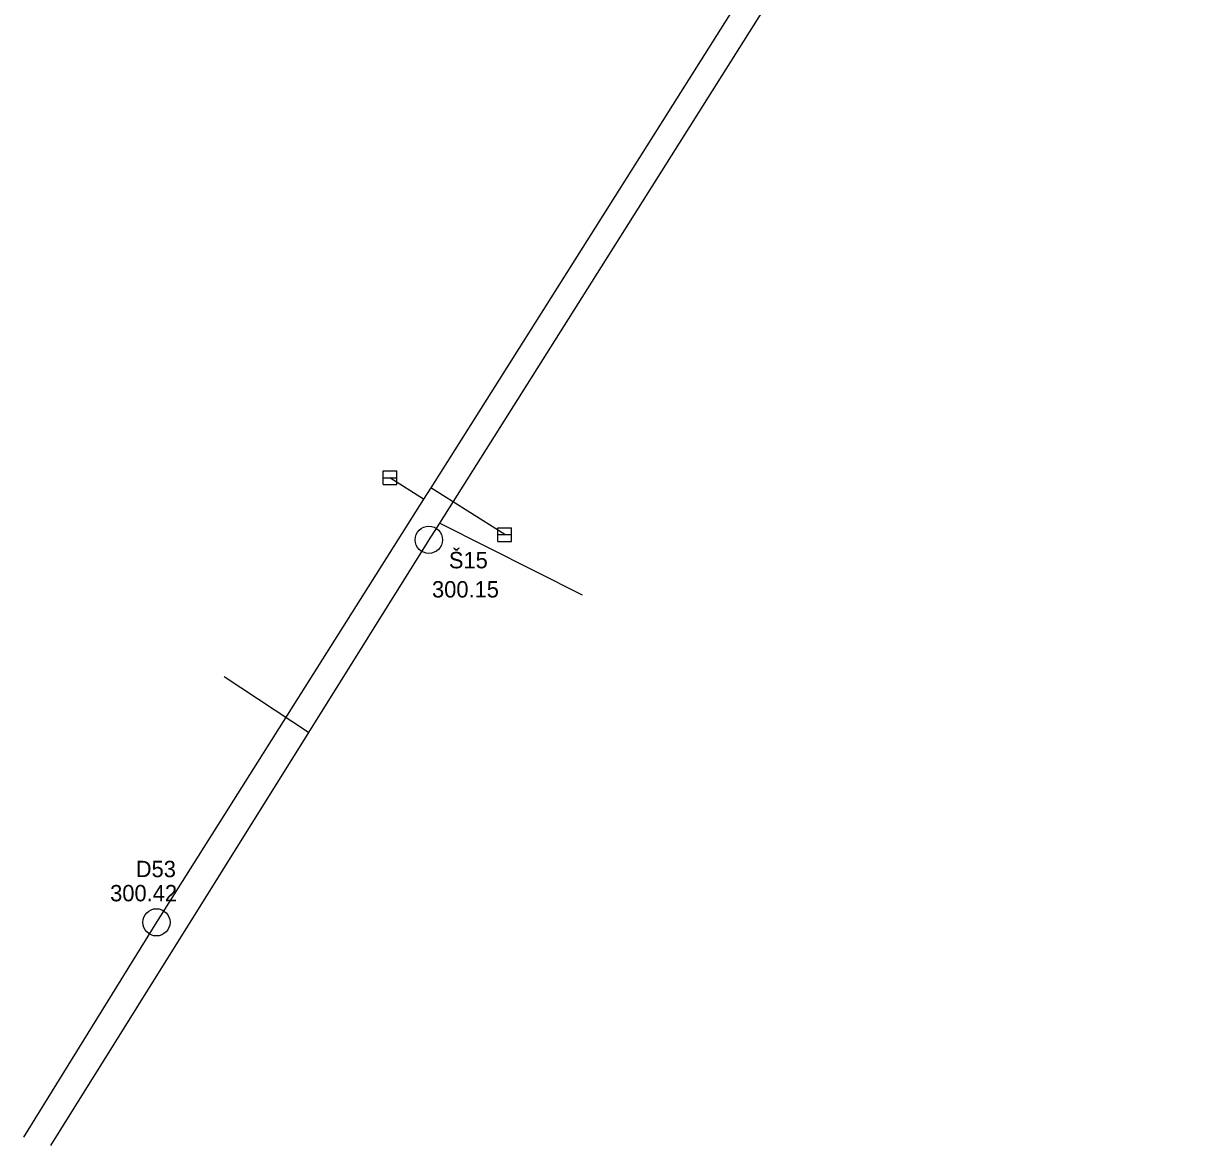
# Model space of a CAD drawing. Extents: x -734099 to -733912, y -1053676 to -1053434.
# Drawn here: x -734087.73 to -734044.58, y -1053675.88 to -1053634.74 of the extents above; entities that cross this region are included whole.
import ezdxf

# ---------------------------------------------------------------- set-up
doc = ezdxf.new("R2010")
doc.units = 0
for name, color, linetype in [('D-kanalizace', 7, 'Continuous'), ('D-ostatni_POPIS', 7, 'Continuous'), ('D-sachta', 7, 'Continuous'), ('D-ul_vpust', 7, 'Continuous'), ('S-kanalizace', 7, 'Continuous'), ('S-ostatni_POPIS', 7, 'Continuous'), ('S-sachta', 7, 'Continuous')]:
    doc.layers.add(name, color=color, linetype=linetype)

msp = doc.modelspace()

# ---------------------------------------------------------------- linework, layer by layer
at = {"layer": 'D-kanalizace'}
for points in [[(-734057.19, -1053460.85), (-734062.51, -1053493.33), (-734067.13, -1053518.49), (-734067.73, -1053542.43), (-734062.81, -1053568.67), (-734051.84, -1053603.59), (-734044.58, -1053615.35), (-734045.524, -1053616.125), (-734052.542, -1053621.881), (-734055.43, -1053624.25), (-734072.802, -1053651.768), (-734073.062, -1053652.179), (-734082.86, -1053667.7), (-734087.73, -1053675.58)], [(-734073.062, -1053652.179), (-734074.296, -1053651.393)], [(-734070.09, -1053653.48), (-734072.802, -1053651.768)]]:
    msp.add_lwpolyline(points, dxfattribs=at)
at = {"layer": 'D-sachta'}
msp.add_circle((-734082.86, -1053667.7), 0.5, dxfattribs=at)
at = {"layer": 'D-ul_vpust'}
for p, q in [((-734074.546, -1053651.143), (-734074.046, -1053651.143)), ((-734074.546, -1053651.643), (-734074.546, -1053651.143)), ((-734074.046, -1053651.643), (-734074.046, -1053651.143)), ((-734074.546, -1053651.393), (-734074.046, -1053651.393)), ((-734074.546, -1053651.643), (-734074.046, -1053651.643)), ((-734070.34, -1053653.23), (-734069.84, -1053653.23)), ((-734070.34, -1053653.73), (-734070.34, -1053653.23)), ((-734070.34, -1053653.48), (-734069.84, -1053653.48)), ((-734069.84, -1053653.73), (-734069.84, -1053653.23)), ((-734070.34, -1053653.73), (-734069.84, -1053653.73))]:
    msp.add_line(p, q, dxfattribs=at)
at = {"layer": 'S-kanalizace'}
for points in [[(-734055.72, -1053626.47), (-734057.409, -1053629.149), (-734072.485, -1053653.059), (-734072.87, -1053653.67), (-734077.279, -1053660.733), (-734086.738, -1053675.884)], [(-734067.24, -1053655.7), (-734072.485, -1053653.059)], [(-734077.279, -1053660.733), (-734080.379, -1053658.701)]]:
    msp.add_lwpolyline(points, dxfattribs=at)
at = {"layer": 'S-sachta'}
msp.add_circle((-734072.87, -1053653.67), 0.5, dxfattribs=at)

# ---------------------------------------------------------------- texts
at = {"layer": 'D-ostatni_POPIS'}
for s, p in [('D53', (-734083.615, -1053666.044)), ('300.42', (-734084.555, -1053666.93))]:
    msp.add_text(s, height=0.6, dxfattribs=at).set_placement(p)
at = {"layer": 'S-ostatni_POPIS'}
for s, p in [('Š15', (-734072.136, -1053654.718)), ('300.15', (-734072.754, -1053655.787))]:
    msp.add_text(s, height=0.6, dxfattribs=at).set_placement(p)

doc.saveas('drawing.dxf')
